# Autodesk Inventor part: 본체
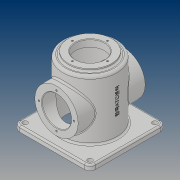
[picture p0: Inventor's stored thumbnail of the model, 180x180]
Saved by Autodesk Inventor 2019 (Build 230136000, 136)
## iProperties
Created: 2019-03
Part Number: 본체
Material: 일반
Document SubType Name: Modeling
Designer: PC312-18
Density: 1 g/cm^3
Appearance: 기본값
Mass: 414.937 g
Surface Area: 1160.05 cm^2
Volume: 414.937 cm^3
Author: PC312-18
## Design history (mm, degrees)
sketch "스케치1"
  geometry: L1 (0, 0)-(120, 0); L2 (120, 0)-(120, 50); L3 (120, 50)-(0, 50); L4 (0, 50)-(0, 0)
  constraints: 8 end point, 2 horizontal, 2 vertical
  dimensions: "d0" = 120 distance of L1.start L1.end; "d1" = 100 diameter of L3 L1
revolve "회전1" sketch "스케치1" stored, may be unused: angle "d2" = 90 deg
sketch "스케치2"
  geometry: L1 (0, 0)-(112, 0); L2 (112, 0)-(112, 45); L3 (112, 45)-(0, 45); L4 (0, -50)-(0, 50) reference; L5 (0, 0)-(0, 45)
  constraints: 8 end point, 2 horizontal, 2 vertical, 1 point on line
  dimensions: "d3" = 112 distance of L1.start L1.end; "d4" = 90 diameter of L3 L1
revolve "회전2" sketch "스케치2" stored, may be unused: angle "d5" = 90 deg
fillet "모깎기1" dims "d6" = 5
fillet "모깎기2" dims "d7" = 3
sketch "스케치3"
  geometry: L1 (-70, -70)-(70, -70); L2 (70, -70)-(70, 70); L3 (70, 70)-(-70, 70); L4 (-70, 70)-(-70, -70); L5 (-70, -70)-(70, 70); L6 (70, -70)-(-70, 70); C1 r 45 at (0, 0) reference; C2 r 50 at (0, 0) reference; 1 further point
  constraints: 12 end point, 2 midpoint, 2 parallel, 1 horizontal, 1 perpendicular
  dimensions: "d8" = 140 distance of L3.end L2.end; "d9" = 140 distance of L2.end L1.end
extrude "돌출1" join sketch "스케치3" distance "d10" = 10; taper "d11" = 0 deg
node "작업 평면1"
sketch "스케치4"
  geometry: C1 r 40 at (0, 0); 1 further point
  constraints: 1 centre point, 1 coincident
  dimensions: "d13" = 80 diameter of C1
extrude "돌출2" join sketch "스케치4" stored distance "d14" = 10; taper "d15" = 0 deg
sketch "스케치5"
  geometry: C1 r 27 at (0, 0); 1 further point
  constraints: 1 centre point, 1 coincident
  dimensions: "d16" = 54 diameter of C1
extrude "돌출3" cut sketch "스케치5" extent not by distance; stored distance "d17" = 10; taper "d18" = 0 deg
node "작업 평면2"
sketch "스케치6"
  geometry: L1 (70, 0)-(-70, 0) reference; C1 r 40 at (0, 60); 2 further points
  constraints: 1 centre point, 1 midpoint, 1 vertical alignment
  dimensions: "d20" = 80 diameter of C1; "d21" = 60 distance from line of L1 C1.centre
extrude "돌출4" join sketch "스케치6" stored distance "d22" = 10; taper "d23" = 0 deg
sketch "스케치7"
  geometry: L1 (70, -60)-(-70, -60) reference; C1 r 40 at (0, 0) reference; 3 further points
  constraints: 1 midpoint, 1 vertical alignment
  dimensions: "d24" = 32.5 distance of C1.centre point (0, 32.5)
hole "구멍1" sketch "스케치7" at (0, 32.5) diameter "d25" = 3.242; stored, may be unused: countersink angle "d29" = 90 deg, drill point angle "d31" = 118 deg; dims "d26" = 8, "d27" = 4, "d28" = 2, "d30" = 10
sketch "스케치8"
  geometry: C1 r 27 at (0, 0); C2 r 40 at (0, 0) reference; 1 further point
  constraints: 1 centre point, 1 concentric
  dimensions: "d35" = 54 diameter of C1
extrude "돌출5" cut sketch "스케치8" extent not by distance; stored distance "d36" = 10; taper "d37" = 0 deg
sketch "스케치9"
  geometry: 2 further points
  constraints: 1 vertical alignment
  dimensions: "d38" = 32.5 distance of point (0, 0) point (0, 32.5)
hole "구멍2" sketch "스케치9" at (0, 32.5) diameter "d39" = 3.242; stored, may be unused: countersink angle "d43" = 90 deg, drill point angle "d45" = 118 deg; dims "d40" = 8, "d41" = 4, "d42" = 2, "d44" = 10
fillet "모깎기3" dims "d49" = 10
chamfer "모따기1" distance "d50" = 1; stored, may be unused: second distance "d51" = 2, angle "d52" = 45 deg
sketch "스케치10"
  geometry: A1 r 10 centre (60, -60) between (60, -70) and (70, -60) reference; A2 r 10 centre (60, 60) between (70, 60) and (60, 70) reference; A3 r 10 centre (-60, -60) between (-70, -60) and (-60, -70) reference; A4 r 10 centre (-60, 60) between (-60, 70) and (-70, 60) reference; 5 further points
  constraints: 4 coincident
hole "구멍3" sketch "스케치10" at (60, -60), (60, 60), (-60, -60), (-60, 60) diameter "d53" = 9; stored, may be unused: countersink angle "d57" = 90 deg, drill point angle "d59" = 118 deg; dims "d54" = 8, "d55" = 4, "d56" = 2, "d58" = 10
fillet "모깎기4" dims "d60" = 3
fillet "모깎기5" dims "d61" = 3
node "작업 평면3"
sketch "스케치11"
  geometry: L1 (0, -60)-(0, 60) reference; 3 further points
  constraints: 1 horizontal alignment, 1 midpoint, 1 other
  dimensions: "d63" = 70 distance from line of L1 point (70, 0)
feature "엠보싱1" sketch "스케치11" dims "d64" = 0.5, "d65" = 0
node "솔리드1"
pattern_circular "원형 패턴1" dims angle "d33" = 360 deg
mirror "미러1"
pattern_circular "원형 패턴2" dims angle "d47" = 360 deg
node "투영된 루프1"
other parameters: "d12" = 125, "d19" = 62
